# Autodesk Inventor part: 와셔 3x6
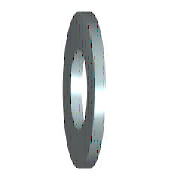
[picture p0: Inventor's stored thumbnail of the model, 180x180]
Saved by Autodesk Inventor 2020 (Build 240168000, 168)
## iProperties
Created: 2012-02
Part Number: 와셔 3x6
Material: 강철, 연강
Description: 평면 와셔
Document SubType Name: Modeling
Standard: KS B 1326
Designer: mduedu
Standards Organization: KS
Language: ko-KR
Size Designation: 3x6
Categories: <MemberInstance><Categories><Category DisplayName="조임쇠" InternalName="e4da775c-781d-43d5-af7c-5136215cf5a6" Mnemonic="FSTN"><Category DisplayName="와셔" InternalN
Density: 7.86 g/cm^3
Mass: 0.0795112 g
Surface Area: 0.54915 cm^2
Volume: 0.0101159 cm^3
Appearance: 파란색 - 벽 페인트 - 광택
IsCustomPart: 0
Author: mduedu
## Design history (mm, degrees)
sketch "스케치"
  geometry: C1 r 3 at (0, 0); C2 r 1.6 at (0, 0); 1 further point
  constraints: 2 centre point, 2 coincident
  dimensions: "d0" = 3.2 diameter of C2 (= SD1); "d1" = 6 diameter of C1 (= SD2)
extrude "본체" new body sketch "스케치" distance "d2" = 0.5 (= SD); taper "d3" = 0 deg
workaxis "Work Axis1"
workplane "Work Plane1"
body "Solid1"
other parameters: "SD1" = 3.2 [user parameter; used in 1 equation term], "SD2" = 6 [user parameter; used in 1 equation term], "SD" = 0.5 [user parameter; used in 1 equation term], "d4" = 0, "d5" = 0, "d6" = 0, "d7" = 0, "NND" = 3 [user parameter]
